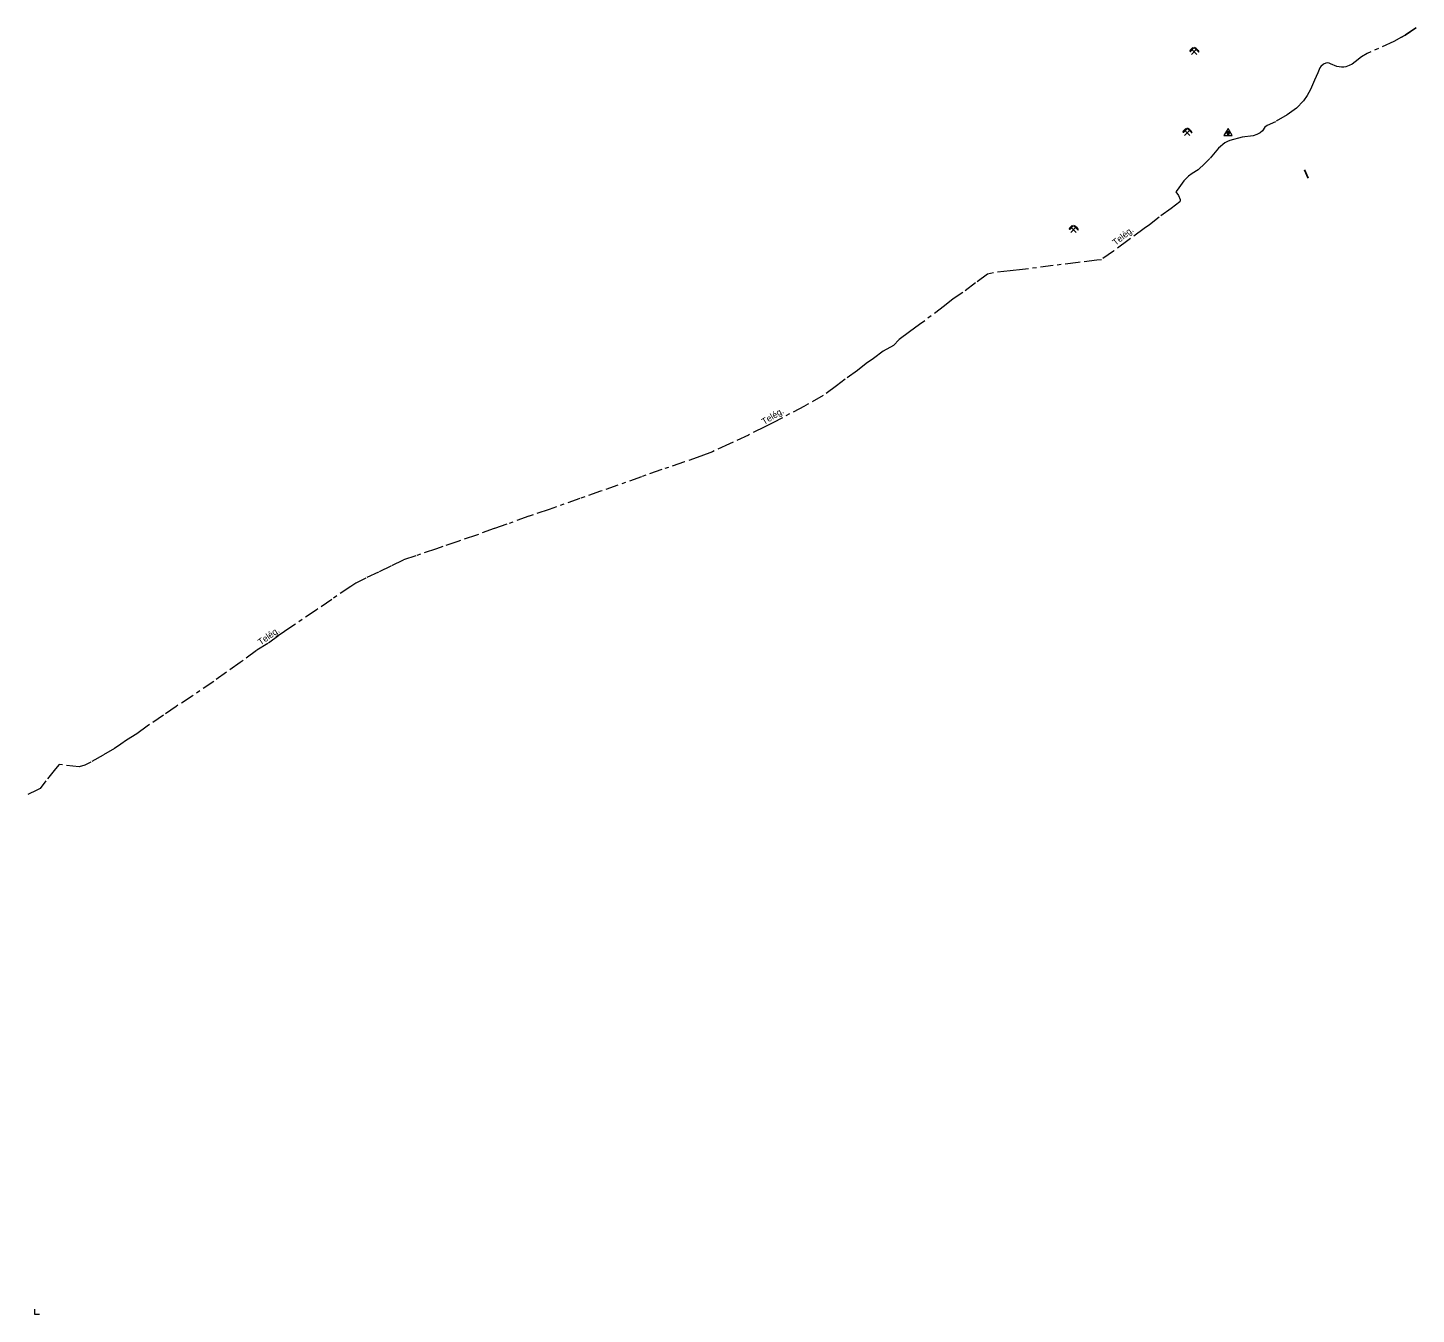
# Model space of a CAD drawing. Extents: x 175.9 to 230.5, y 8394.8 to 8450.8.
# Drawn here: x 176.43 to 210.97, y 8394.83 to 8426.85 of the extents above; entities that cross this region are included whole.
import ezdxf
from ezdxf.enums import TextEntityAlignment as Align

# ---------------------------------------------------------------- set-up
doc = ezdxf.new("R2010")
doc.units = 0
doc.header["$LTSCALE"] = 0.064
doc.linetypes.add('DOT_DASHED', pattern=[7.7, 5, -1.2, 0.3, -1.2])
for name, color, linetype, lineweight in [('24', 7, 'Continuous', 25), ('3', 7, 'Continuous', 13), ('49', 7, 'Continuous', 25), ('57', 7, 'DOT_DASHED', 13), ('63', 7, 'Continuous', 13)]:
    doc.layers.add(name, color=color, linetype=linetype, lineweight=lineweight)
doc.layers.add('61', color=7, linetype='Continuous')

msp = doc.modelspace()

# ---------------------------------------------------------------- hatches: boundary and pattern name
at = {"layer": '3'}
msp.add_hatch(color=256, dxfattribs=at).paths.add_polyline_path([(206.3346, 8424.2561), (206.2346, 8424.2561), (206.2846, 8424.1701)])
at = {"layer": '49'}
for points in [[(205.4093, 8426.356), (205.4287, 8426.3368), (205.3493, 8426.2576), (205.3455, 8426.2672), (205.3455, 8426.2768), (205.3475, 8426.2904), (205.3533, 8426.3)], [(205.4423, 8426.36), (205.4595, 8426.3522), (205.4769, 8426.3426), (205.4905, 8426.3348), (205.5021, 8426.3252), (205.5177, 8426.3116), (205.5311, 8426.2922), (205.5389, 8426.2788), (205.5467, 8426.2632), (205.5543, 8426.2478)], [(205.2368, 8424.343), (205.2562, 8424.3238), (205.1768, 8424.2446), (205.173, 8424.2542), (205.173, 8424.2638), (205.175, 8424.2774), (205.1808, 8424.287)], [(205.2698, 8424.347), (205.287, 8424.3392), (205.3044, 8424.3296), (205.318, 8424.3218), (205.3296, 8424.3122), (205.3452, 8424.2986), (205.3586, 8424.2792), (205.3664, 8424.2658), (205.3742, 8424.2502), (205.3818, 8424.2348)], [(202.4075, 8421.927), (202.4269, 8421.9078), (202.3475, 8421.8286), (202.3437, 8421.8382), (202.3437, 8421.8478), (202.3457, 8421.8614), (202.3515, 8421.871)], [(202.4405, 8421.931), (202.4577, 8421.9232), (202.4751, 8421.9136), (202.4887, 8421.9058), (202.5003, 8421.8962), (202.5159, 8421.8826), (202.5293, 8421.8632), (202.5371, 8421.8498), (202.5449, 8421.8342), (202.5525, 8421.8188)]]:
    msp.add_hatch(color=256, dxfattribs=at).paths.add_polyline_path(points)

# ---------------------------------------------------------------- linework, layer by layer
at = {"layer": '24'}
msp.add_line((208.1866, 8423.3092), (208.278, 8423.1021), dxfattribs=at)
at = {"layer": '3'}
for points in [[(206.3846, 8424.1701), (206.2846, 8424.3431), (206.1846, 8424.1701)], [(206.3346, 8424.2561), (206.2346, 8424.2561), (206.2846, 8424.1701)]]:
    msp.add_lwpolyline(points, close=True, dxfattribs=at)
at = {"layer": '49'}
for p, q in [((205.3725, 8426.182), (205.4963, 8426.3058)), ((205.5099, 8426.182), (205.3919, 8426.3)), ((205.2, 8424.169), (205.3238, 8424.2928)), ((205.3374, 8424.169), (205.2194, 8424.287)), ((202.3707, 8421.753), (202.4945, 8421.8768)), ((202.5081, 8421.753), (202.3901, 8421.871))]:
    msp.add_line(p, q, dxfattribs=at)
for points in [[(205.4093, 8426.356), (205.4287, 8426.3368), (205.3493, 8426.2576), (205.3455, 8426.2672), (205.3455, 8426.2768), (205.3475, 8426.2904), (205.3533, 8426.3)], [(205.4423, 8426.36), (205.4595, 8426.3522), (205.4769, 8426.3426), (205.4905, 8426.3348), (205.5021, 8426.3252), (205.5177, 8426.3116), (205.5311, 8426.2922), (205.5389, 8426.2788), (205.5467, 8426.2632), (205.5543, 8426.2478)], [(205.2368, 8424.343), (205.2562, 8424.3238), (205.1768, 8424.2446), (205.173, 8424.2542), (205.173, 8424.2638), (205.175, 8424.2774), (205.1808, 8424.287)], [(205.2698, 8424.347), (205.287, 8424.3392), (205.3044, 8424.3296), (205.318, 8424.3218), (205.3296, 8424.3122), (205.3452, 8424.2986), (205.3586, 8424.2792), (205.3664, 8424.2658), (205.3742, 8424.2502), (205.3818, 8424.2348)], [(202.4075, 8421.927), (202.4269, 8421.9078), (202.3475, 8421.8286), (202.3437, 8421.8382), (202.3437, 8421.8478), (202.3457, 8421.8614), (202.3515, 8421.871)], [(202.4405, 8421.931), (202.4577, 8421.9232), (202.4751, 8421.9136), (202.4887, 8421.9058), (202.5003, 8421.8962), (202.5159, 8421.8826), (202.5293, 8421.8632), (202.5371, 8421.8498), (202.5449, 8421.8342), (202.5525, 8421.8188)]]:
    msp.add_lwpolyline(points, close=True, dxfattribs=at)
at = {"layer": '57'}
for points in [[(210.597, 8426.6129), (210.6908, 8426.6673), (210.9664, 8426.8486), (210.6908, 8426.6673), (210.597, 8426.6129), (210.4082, 8426.5034), (209.7473, 8426.212), (209.606, 8426.1256), (209.4511, 8425.9981), (209.369, 8425.9389), (209.3006, 8425.9071), (209.2186, 8425.8797), (209.1639, 8425.8706), (209.1047, 8425.8706), (208.9907, 8425.8843), (208.8357, 8425.9526), (208.8038, 8425.9662), (208.7628, 8425.9753), (208.7172, 8425.9708), (208.6625, 8425.9435), (208.5895, 8425.8868), (208.5699, 8425.8526), (208.5173, 8425.7282), (208.4383, 8425.5415), (208.3341, 8425.3131), (208.25, 8425.1619), (208.1592, 8425.0309), (207.9862, 8424.8509), (207.7576, 8424.6796), (207.465, 8424.5117), (207.2565, 8424.4143), (207.2027, 8424.374), (207.1388, 8424.28), (207.085, 8424.2329), (206.9975, 8424.1926), (206.9067, 8424.1624), (206.6343, 8424.1255), (206.3266, 8424.0427), (206.27, 8424.0152), (206.2022, 8423.9822), (206.0475, 8423.8513), (205.8289, 8423.5926), (205.7112, 8423.4717), (205.5431, 8423.3105), (205.3942, 8423.2182), (205.3, 8423.1544), (205.189, 8423.0402), (205.0165, 8422.8069), (204.9852, 8422.7698), (205.0523, 8422.673), (205.0922, 8422.5717), (205.0982, 8422.5379), (205.0825, 8422.5197), (204.8715, 8422.3505), (204.5679, 8422.1366), (204.3282, 8421.945), (204.1971, 8421.8493), (203.7898, 8421.5531), (203.4318, 8421.2882), (203.1346, 8421.0775), (203.0195, 8421.0679), (202.5537, 8421.0063), (201.9368, 8420.9296), (201.1741, 8420.8336), (200.8673, 8420.8017), (200.4549, 8420.7538), (200.3015, 8420.7155), (200.0011, 8420.4984), (199.6894, 8420.263), (199.4497, 8420.1002), (199.2356, 8419.931), (198.6104, 8419.4627), (198.3611, 8419.284), (198.1054, 8419.0924), (197.9648, 8418.9424), (197.7059, 8418.8019), (197.468, 8418.618), (197.2826, 8418.4935), (197.0716, 8418.3212), (196.7616, 8418.1041), (196.5443, 8417.9349), (196.2161, 8417.6967), (195.7463, 8417.4349), (194.9613, 8417.0175), (194.7599, 8416.9185), (194.354, 8416.7142), (193.8842, 8416.4908), (193.4574, 8416.2976), (193.1729, 8416.1859), (192.7638, 8416.0454), (192.1993, 8415.8528), (191.6943, 8415.674), (190.679, 8415.3152), (190.1613, 8415.1364), (189.3955, 8414.8606), (188.8905, 8414.6946), (188.3455, 8414.4925), (188.0323, 8414.3871), (187.588, 8414.2243), (187.1278, 8414.0679), (186.7549, 8413.9423)], [(186.7549, 8413.9423), (186.5951, 8413.8848), (186.0805, 8413.7092), (185.7673, 8413.6007), (185.4553, 8413.4491), (185.1548, 8413.3022), (184.8384, 8413.1522), (184.5923, 8413.0277), (184.4613, 8412.9479), (183.9896, 8412.6234), (183.6029, 8412.3584), (182.9491, 8411.9124), (182.6743, 8411.7241), (182.4026, 8411.5261), (182.1213, 8411.3538), (181.7139, 8411.0517), (181.3751, 8410.8154), (181.0555, 8410.5824), (180.5167, 8410.2192), (180.1172, 8409.9606), (179.8071, 8409.7404), (179.398, 8409.469), (179.144, 8409.2819), (178.8819, 8409.1191), (178.7445, 8409.0169), (178.5847, 8408.9148), (178.3002, 8408.7488), (177.9945, 8408.5713), (177.8442, 8408.5011), (177.71, 8408.4532), (177.205, 8408.5171), (177.1219, 8408.4085), (176.8758, 8408.1085), (176.7352, 8407.9137), (176.6521, 8407.8754), (176.4281, 8407.77)]]:
    msp.add_lwpolyline(points, dxfattribs=at)
at = {"layer": '63'}
msp.add_lwpolyline([(176.5972, 8394.9581), (176.5972, 8394.8349), (176.7186, 8394.8349)], dxfattribs=at)

# ---------------------------------------------------------------- texts
at = {"layer": '61'}
for rotation, p in [(38.696, (203.7202, 8421.6058)), (31.583, (194.9991, 8417.1176)), (35.102, (182.4656, 8411.6478))]:
    msp.add_text('Telég.', height=0.16, rotation=rotation, dxfattribs=at).set_placement(p, align=Align.CENTER)

doc.saveas('drawing.dxf')
